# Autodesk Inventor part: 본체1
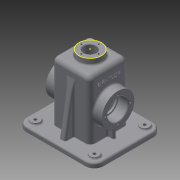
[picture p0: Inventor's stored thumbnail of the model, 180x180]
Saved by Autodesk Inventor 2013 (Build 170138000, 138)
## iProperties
Created: 2016-01
Part Number: 본체1
Material: 일반
Document SubType Name: Modeling
Designer: Administrator
Density: 1 g/cm^3
Author: Administrator
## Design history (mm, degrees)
sketch "스케치1"
  geometry: 1 further point
sketch "스케치2"
  geometry: L1 (-32.5, 32.5)-(32.5, 32.5); L2 (32.5, 32.5)-(32.5, -32.5); L3 (32.5, -32.5)-(-32.5, -32.5); L4 (-32.5, -32.5)-(-32.5, 32.5); 3 further points
  constraints: 8 end point, 2 midpoint, 2 parallel, 1 horizontal, 1 horizontal alignment, 1 perpendicular, 1 vertical alignment
  dimensions: "d0" = 65 distance of L1.start L1.end; "d2" = 65 distance of L1.end L2.end
extrude "돌출1" new body sketch "스케치2" distance "d3" = 110; taper "d4" = 0 deg
fillet "모깎기1" dims "d5" = 8
fillet "모깎기2" dims "d6" = 8
feature "쉘1" dims "d7" = 5
sketch "스케치3"
  geometry: C1 r 20 at (0, 0); 1 further point
  constraints: 1 centre point, 1 coincident
  dimensions: "d8" = 40 diameter of C1
extrude "돌출2" join sketch "스케치3" distance "d9" = 10; taper "d10" = 0 deg
feature "면 기울기1" dims angle "d11" = 5 deg
sketch "스케치4"
  geometry: C1 r 19.125 at (0, 0) reference
hole "구멍1" diameter "d14" = 21; stored, may be unused: countersink angle "d18" = 90 deg, drill point angle "d20" = 0 deg; dims "d12" = 10, "d13" = 10, "d15" = 6, "d16" = 4, "d17" = 2, "d19" = 8
sketch "스케치5"
  geometry: L1 (0, 0)-(0, 49) reference; C1 r 27.5 at (55, 24.5); 3 further points
  constraints: 1 centre point, 1 coincident, 1 horizontal alignment, 1 midpoint
  dimensions: "d21" = 55 distance of point (0, 24.5) point (55, 24.5); "d22" = 55 diameter of C1
extrude "돌출3" join sketch "스케치5" distance "d23" = 15; taper "d25" = 0 deg; dims "d24" = 5, "d26" = 0
hole "구멍2" diameter "d29" = 30; stored, may be unused: countersink angle "d33" = 90 deg, drill point angle "d35" = 0 deg; dims "d27" = 10, "d28" = 10, "d30" = 6, "d31" = 35, "d32" = 17, "d34" = 8
sketch "스케치6"
  geometry: L1 (24.5, 32.5)-(-24.5, 32.5) reference; L2 (-32.5, 24.5)-(-32.5, -24.5) reference; L3 (-24.5, -32.5)-(24.5, -32.5) reference; L4 (32.5, -24.5)-(32.5, 24.5) reference; L5 (-65, -57.5)-(65, -57.5); L6 (65, -57.5)-(65, 57.5); L7 (65, 57.5)-(-65, 57.5); L8 (-65, 57.5)-(-65, -57.5); A1 r 8 centre (24.5, 24.5) between (32.5, 24.5) and (24.5, 32.5) reference; A2 r 8 centre (-24.5, 24.5) between (-24.5, 32.5) and (-32.5, 24.5) reference; A3 r 8 centre (-24.5, -24.5) between (-32.5, -24.5) and (-24.5, -32.5) reference; A4 r 8 centre (24.5, -24.5) between (24.5, -32.5) and (32.5, -24.5) reference; 3 further points
  constraints: 8 end point, 2 midpoint, 2 parallel, 1 horizontal, 1 horizontal alignment, 1 perpendicular, 1 vertical alignment
  dimensions: "d36" = 115 distance of L7.end L5.start; "d38" = 130 distance of L6.end L7.end
extrude "돌출4" join sketch "스케치6" distance "d39" = 10; taper "d40" = 0 deg
fillet "모깎기3" dims "d41" = 15
sketch "스케치7"
  geometry: L1 (50, 57.5)-(-50, 57.5) reference; L2 (-65, 42.5)-(-65, -42.5) reference; L3 (-50, -57.5)-(50, -57.5) reference; L4 (65, -42.5)-(65, 42.5) reference; L5 (50, -52.5)-(-50, -52.5); L6 (-60, -42.5)-(-60, 42.5); L7 (-50, 52.5)-(50, 52.5); L8 (60, 42.5)-(60, -42.5); A1 r 15 centre (50, 42.5) between (65, 42.5) and (50, 57.5) reference; A2 r 15 centre (-50, 42.5) between (-50, 57.5) and (-65, 42.5) reference; A3 r 15 centre (-50, -42.5) between (-65, -42.5) and (-50, -57.5) reference; A4 r 15 centre (50, -42.5) between (50, -57.5) and (65, -42.5) reference; A5 r 10 centre (-50, -42.5) between (-60, -42.5) and (-50, -52.5); A6 r 10 centre (-50, 42.5) between (-50, 52.5) and (-60, 42.5); A7 r 10 centre (50, 42.5) between (60, 42.5) and (50, 52.5); A8 r 10 centre (50, -42.5) between (50, -52.5) and (60, -42.5); 1 further point
  constraints: 8 end point, 8 point on circle, 4 centre point, 7 other
  dimensions: "d42" = 5 distance between parallel lines of L3 L5
extrude "돌출5" cut sketch "스케치7" distance "d43" = 2; taper "d44" = 0 deg
sketch "스케치8"
  geometry: C1 r 17.5 at (0, 0) reference; 2 further points
  constraints: 1 horizontal alignment
  dimensions: "d45" = 21 distance of point (21, 0) C1.centre
hole "구멍3" sketch "스케치8" at (21, 0) diameter "d46" = 3.242; stored, may be unused: countersink angle "d50" = 90 deg, drill point angle "d52" = 118 deg; dims "d47" = 8, "d48" = 35, "d49" = 17, "d51" = 10
sketch "스케치9"
  geometry: C1 r 10.5 at (0, 0) reference; 1 further point
  constraints: 1 horizontal alignment
  dimensions: "d56" = 14.5 distance of C1.centre point (-14.5, 0)
hole "구멍4" sketch "스케치9" at (-14.5, 0) diameter "d57" = 2.459; stored, may be unused: countersink angle "d61" = 90 deg, drill point angle "d63" = 118 deg; dims "d58" = 7, "d59" = 35, "d60" = 17, "d62" = 9
sketch "스케치10"
  geometry: C1 r 7.5 at (-50, -42.5); C2 r 7.5 at (-50, 42.5); C3 r 7.5 at (50, 42.5); C4 r 7.5 at (50, -42.5); A1 r 15 centre (-50, 42.5) between (-50, 57.5) and (-65, 42.5) reference; A2 r 15 centre (-50, -42.5) between (-65, -42.5) and (-50, -57.5) reference; A3 r 15 centre (50, -42.5) between (50, -57.5) and (65, -42.5) reference; A4 r 15 centre (50, 42.5) between (65, 42.5) and (50, 57.5) reference; 1 further point
  constraints: 4 centre point, 4 coincident
  dimensions: "d67" = 15 diameter of C1; "d68" = 15 diameter of C2; "d69" = 15 diameter of C3; "d70" = 15 diameter of C4
extrude "돌출6" join sketch "스케치10" distance "d71" = 3; taper "d72" = 0 deg
hole "구멍5" diameter "d75" = 5; stored, may be unused: countersink angle "d79" = 90 deg, drill point angle "d81" = 118 deg; dims "d73" = 10, "d74" = 10, "d76" = 7, "d77" = 35, "d78" = 17, "d80" = 9
sketch "스케치11"
  geometry: L1 (-47.5, 37.5)-(-30.5, 37.5) reference; L2 (-30.5, 37.5)-(-30.5, 40) reference; L3 (-30.5, 40)-(-27.5, 40) reference; L4 (-27.5, 40)-(-27.5, 0) reference; L5 (-27.5, 0)-(-60, 0) reference; L6 (-60, 0)-(-60, 2) reference; L7 (-60, 2)-(-65, 2) reference; L8 (-65, 2)-(-65, 10) reference; L9 (-65, 10)-(-32.5, 10) reference; L10 (-32.5, 10)-(-32.5, 27.5) reference; L11 (-32.5, 27.5)-(-47.5, 27.5) reference; L12 (-47.5, 27.5)-(-47.5, 32.379) reference; L13 (-47.5, 32.379)-(-37.5, 32.379) reference; L14 (-37.5, 32.379)-(-36.526, 34) reference; L15 (-36.526, 34)-(-37.5, 35.621) reference; L16 (-37.5, 35.621)-(-47.5, 35.621) reference; L17 (-47.5, 35.621)-(-47.5, 37.5) reference; L18 (47.5, 27.5)-(32.5, 27.5) reference; L19 (32.5, 27.5)-(32.5, 10) reference; L20 (32.5, 10)-(65, 10) reference; L21 (65, 10)-(65, 2) reference; L22 (65, 2)-(60, 2) reference; L23 (60, 2)-(60, 0) reference; L24 (60, 0)-(27.5, 0) reference; L25 (27.5, 0)-(27.5, 40) reference; L26 (30.5, 40)-(30.5, 37.5) reference; L27 (30.5, 37.5)-(47.5, 37.5) reference; L28 (47.5, 37.5)-(47.5, 35.621) reference; L29 (47.5, 35.621)-(37.5, 35.621) reference; L30 (37.5, 35.621)-(36.526, 34) reference; L31 (36.526, 34)-(37.5, 32.379) reference; L32 (37.5, 32.379)-(47.5, 32.379) reference; L33 (47.5, 32.379)-(47.5, 27.5) reference; L34 (19.125, 120)-(20, 110) reference; L35 (20, 110)-(24.5, 110) reference; L36 (32.5, 102)-(32.5, 82.5) reference; L37 (32.5, 82.5)-(47.5, 82.5) reference; L38 (47.5, 82.5)-(47.5, 77.621) reference; L39 (47.5, 77.621)-(37.5, 77.621) reference; L40 (37.5, 77.621)-(36.526, 76) reference; L41 (36.526, 76)-(37.5, 74.379) reference; L42 (37.5, 74.379)-(47.5, 74.379) reference; L43 (47.5, 74.379)-(47.5, 72.5) reference; L44 (47.5, 72.5)-(30.5, 72.5) reference; L45 (30.5, 72.5)-(30.5, 70) reference; L46 (27.5, 70)-(27.5, 102) reference; L47 (24.5, 105)-(10.5, 105) reference; L48 (10.5, 105)-(10.5, 120) reference; L49 (10.5, 120)-(13.271, 120) reference; L50 (13.271, 120)-(13.271, 111) reference; L51 (13.271, 111)-(14.5, 110.261) reference; L52 (14.5, 110.261)-(15.73, 111) reference; L53 (15.73, 111)-(15.73, 120) reference; L54 (15.73, 120)-(19.125, 120) reference; L55 (-20, 110)-(-19.125, 120) reference; L56 (-19.125, 120)-(-15.73, 120) reference; L57 (-15.73, 120)-(-15.73, 111) reference; L58 (-15.73, 111)-(-14.5, 110.261) reference; L59 (-14.5, 110.261)-(-13.271, 111) reference; L60 (-13.271, 111)-(-13.271, 120) reference; L61 (-13.271, 120)-(-10.5, 120) reference; L62 (-10.5, 120)-(-10.5, 105) reference; L63 (-10.5, 105)-(-24.5, 105) reference; L64 (-27.5, 102)-(-27.5, 70) reference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; A1 r 8 centre (24.5, 102) between (32.5, 102) and (24.5, 110) reference; A2 r 3 centre (24.5, 102) between (27.5, 102) and (24.5, 105) reference; A3 r 3 centre (-24.5, 102) between (-24.5, 105) and (-27.5, 102) reference; A4 r 8 centre (-24.5, 102) between (-24.5, 110) and (-32.5, 102) reference; 1 further point
  constraints: 2 end point, 1 point on line, 1 vertical
  dimensions: "d82" = 15 distance between parallel lines of L77 L25
feature "리브1" sketch "스케치11" dims "d83" = 1, "d84" = 6, "d85" = 0, "d86" = 0, "d87" = 1, "d88" = 1
sketch "스케치12"
  geometry: L1 (13.271, 111)-(14.5, 110.261) reference; L2 (14.5, 110.261)-(15.73, 111) reference; L3 (15.73, 111)-(15.73, 120) reference; L4 (15.73, 120)-(19.125, 120) reference; L5 (19.125, 120)-(20, 110) reference; L6 (20, 110)-(24.5, 110) reference; L7 (32.5, 102)-(32.5, 10) reference; L8 (32.5, 10)-(57.5, 10) reference; L9 (57.5, 10)-(57.5, 2) reference; L10 (57.5, 2)-(52.5, 2) reference; L11 (52.5, 2)-(52.5, 0) reference; L12 (52.5, 0)-(27.5, 0) reference; L13 (27.5, 0)-(27.5, 102) reference; L14 (24.5, 105)-(10.5, 105) reference; L15 (10.5, 105)-(10.5, 120) reference; L16 (10.5, 120)-(13.271, 120) reference; L17 (13.271, 120)-(13.271, 111) reference; L18 (-24.5, 110)-(-20, 110) reference; L19 (-20, 110)-(-19.125, 120) reference; L20 (-19.125, 120)-(-15.73, 120) reference; L21 (-15.73, 120)-(-15.73, 111) reference; L22 (-15.73, 111)-(-14.5, 110.261) reference; L23 (-14.5, 110.261)-(-13.271, 111) reference; L24 (-13.271, 111)-(-13.271, 120) reference; L25 (-13.271, 120)-(-10.5, 120) reference; L26 (-10.5, 120)-(-10.5, 105) reference; L27 (-10.5, 105)-(-24.5, 105) reference; L28 (-27.5, 102)-(-27.5, 0) reference; L29 (-27.5, 0)-(-52.5, 0) reference; L30 (-52.5, 0)-(-52.5, 2) reference; L31 (-52.5, 2)-(-57.5, 2) reference; L32 (-57.5, 2)-(-57.5, 10) reference; L33 (-57.5, 10)-(-32.5, 10) reference; L34 (-32.5, 10)-(-32.5, 102) reference; L35 (-47.5, 10)-(-32.5, 95.069); A1 r 8 centre (24.5, 102) between (32.5, 102) and (24.5, 110) reference; A2 r 3 centre (24.5, 102) between (27.5, 102) and (24.5, 105) reference; A3 r 8 centre (-24.5, 102) between (-24.5, 110) and (-32.5, 102) reference; A4 r 3 centre (-24.5, 102) between (-24.5, 105) and (-27.5, 102) reference; 1 further point
  constraints: 2 end point, 2 point on line, 1 horizontal alignment
  dimensions: "d89" = 10 distance of L35.start L32.end; "d90" = 10 deg angle of L35 L32
feature "리브2" sketch "스케치12" dims "d91" = 1, "d92" = 10, "d93" = 0, "d94" = 0, "d95" = 1, "d96" = 1
fillet "모깎기4" dims "d97" = 0.3
node "작업 평면1"
sketch "스케치13"
  geometry: L1 (-18, 43.625)-(-18, 5.375) reference; L2 (0, -8)-(92, -8) reference; 2 further points
  constraints: 1 other
  dimensions: "d99" = 27 distance from line of point (9, 24.5) L1; "d100" = 32.5 distance from line of point (9, 24.5) L2
feature "엠보싱1" sketch "스케치13" dims "d101" = 0.5, "d102" = 0
chamfer "모따기1" distance "d103" = 1; stored, may be unused: second distance "d104" = 2, angle "d105" = 45 deg
chamfer "모따기2" distance "d106" = 1; stored, may be unused: second distance "d107" = 2, angle "d108" = 45 deg
chamfer "모따기3" distance "d109" = 1; stored, may be unused: second distance "d110" = 2, angle "d111" = 45 deg
fillet "모깎기5" dims "d112" = 3
fillet "모깎기6" dims "d113" = 3
fillet "모깎기7" dims "d114" = 3
fillet "모깎기8" dims "d115" = 3
fillet "모깎기9" dims "d116" = 3
fillet "모깎기10" dims "d117" = 3
fillet "모깎기11" dims "d118" = 3
fillet "모깎기12" dims "d119" = 1
node "솔리드1"
mirror "대칭1"
pattern_circular "원형 패턴1" dims angle "d54" = 360 deg
mirror "대칭2"
pattern_circular "원형 패턴2" dims angle "d65" = 360 deg
mirror "대칭3"
mirror "대칭4"
mirror "대칭5"
mirror "대칭6"
node "절단 모서리 투영1"
node "절단 모서리 투영2"
other parameters: "d98" = 11.25
